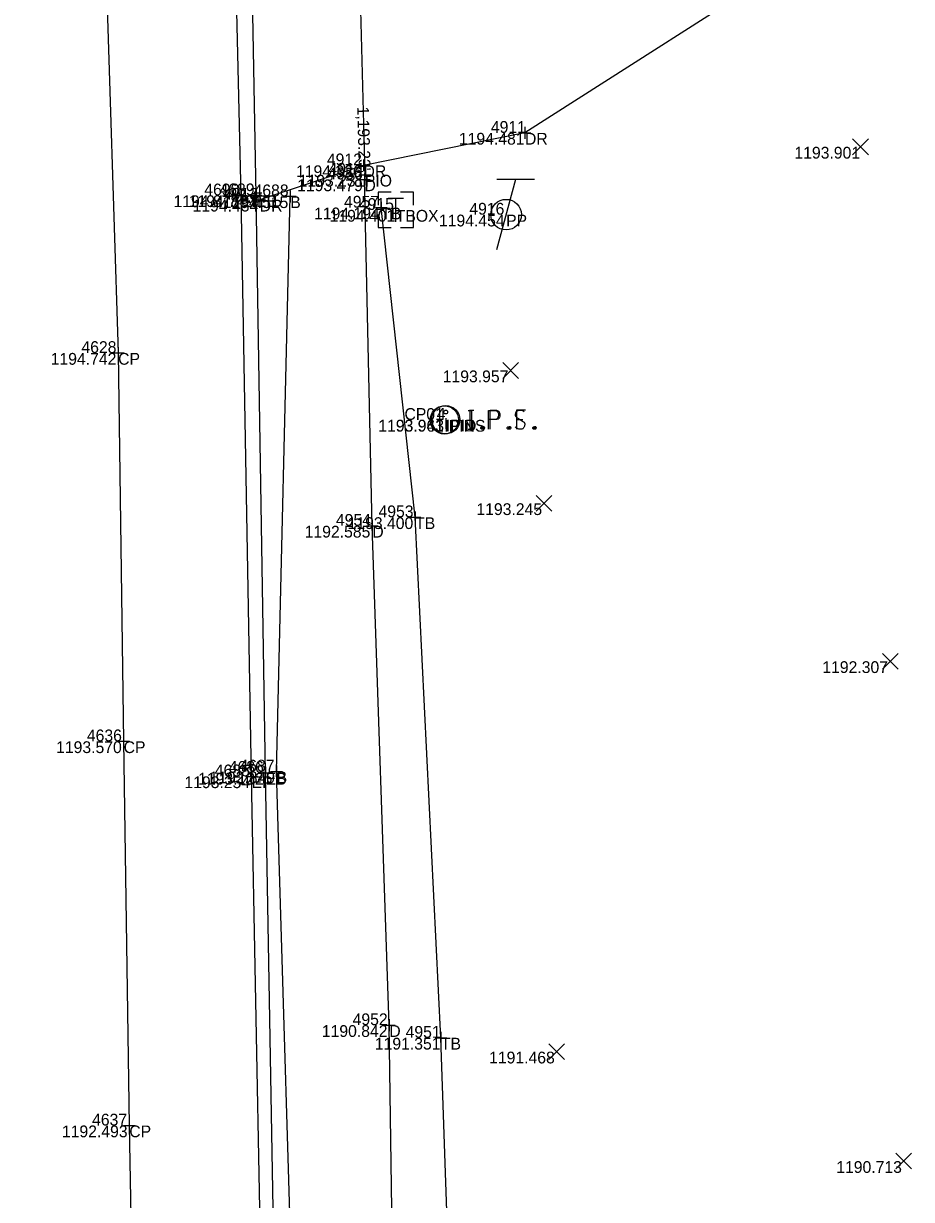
# Model space of a CAD drawing. Extents: x 2044996 to 2050343, y 455232 to 458054.
# Drawn here: x 2047638.7 to 2047714.1, y 456240.2 to 456340.1 of the extents above; entities that cross this region are included whole.
import ezdxf

# ---------------------------------------------------------------- set-up
doc = ezdxf.new("R2010")
doc.units = 0
for name, color, linetype in [('DR_X_Ditch', 7, 'Continuous'), ('DR_X_Elev_Flow', 7, 'Continuous'), ('DR_X_Storm_Sewer', 7, 'Continuous'), ('DT_X_Contour_Minor', 7, 'Continuous'), ('DT_X_Contour_Text', 7, 'Continuous'), ('DT_X_Spot_Elev', 7, 'Continuous'), ('DT_X_TIN_Hull', 7, 'Continuous'), ('DT_X_Triangles', 7, 'Continuous'), ('DT_X_Void', 7, 'Continuous'), ('PV_X_COP', 7, 'Continuous'), ('PV_X_Driveway', 7, 'Continuous'), ('PV_X_EOP', 7, 'Continuous'), ('PV_X_Shoulder_Aggregate', 7, 'Continuous'), ('SC_Scratch1', 7, 'Continuous'), ('SV_P_Mon_Cells_Set', 7, 'Continuous'), ('SV_X_Break_Lines', 7, 'Continuous'), ('SV_X_Top_of_Bank', 7, 'Continuous'), ('UT_X_Electric_Cells', 7, 'Continuous'), ('XS_X_Ground_Line', 7, 'Continuous')]:
    doc.layers.add(name, color=color, linetype=linetype)

msp = doc.modelspace()

# ---------------------------------------------------------------- linework, layer by layer
at = {"layer": 'DR_X_Ditch'}
msp.add_lwpolyline([(2047671.117, 455981.962), (2047672.134, 456029.553), (2047671.987, 456077.978), (2047672.773, 456128.444), (2047671.222, 456171.914), (2047670.3, 456214.023), (2047669.722, 456255.021), (2047668.278, 456297.447), (2047667.609, 456326.875)], dxfattribs=at)
at = {"layer": 'DR_X_Elev_Flow'}
for p, q in [((2047667.145, 456327.273), (2047668.145, 456327.273)), ((2047667.645, 456327.773), (2047667.645, 456326.773)), ((2047667.645, 456327.273), (2047667.645, 456327.273))]:
    msp.add_line(p, q, dxfattribs=at)
at = {"layer": 'DR_X_Storm_Sewer'}
msp.add_line((2047665.559, 456406.889), (2047667.645, 456327.273), dxfattribs=at)
at = {"layer": 'DT_X_Spot_Elev'}
for p, q in [((2047709.079, 456328.976), (2047710.413, 456330.311)), ((2047709.079, 456330.311), (2047710.413, 456328.976)), ((2047679.369, 456309.975), (2047680.703, 456311.31)), ((2047679.369, 456311.31), (2047680.703, 456309.975)), ((2047682.199, 456298.694), (2047683.533, 456300.029)), ((2047682.199, 456300.029), (2047683.533, 456298.694)), ((2047711.612, 456285.272), (2047712.945, 456286.607)), ((2047711.612, 456286.607), (2047712.945, 456285.272)), ((2047683.267, 456252.103), (2047684.6, 456253.438)), ((2047683.267, 456253.438), (2047684.6, 456252.103)), ((2047712.742, 456242.801), (2047714.075, 456244.136)), ((2047712.742, 456244.136), (2047714.075, 456242.801))]:
    msp.add_line(p, q, dxfattribs=at)
at = {"layer": 'DT_X_TIN_Hull'}
for p, q in [((2047669.617, 456325.283), (2047670.917, 456325.283)), ((2047670.267, 456323.283), (2047670.267, 456325.283)), ((2047670.267, 456324.283), (2047670.267, 456324.283))]:
    msp.add_line(p, q, dxfattribs=at)
for points in [[(2047669.867, 456325.783), (2047668.767, 456325.783), (2047668.767, 456324.683)], [(2047671.767, 456324.683), (2047671.767, 456325.783), (2047670.667, 456325.783)], [(2047668.767, 456323.883), (2047668.767, 456322.783), (2047669.867, 456322.783)], [(2047670.667, 456322.783), (2047671.767, 456322.783), (2047671.767, 456323.883)]]:
    msp.add_lwpolyline(points, dxfattribs=at)
at = {"layer": 'DT_X_Void'}
for p, q in [((2047681.246, 456331.331), (2047681.246, 456330.331)), ((2047680.746, 456330.831), (2047681.746, 456330.831)), ((2047681.246, 456330.831), (2047681.246, 456330.831)), ((2047667.534, 456328.571), (2047667.534, 456327.571)), ((2047667.034, 456328.071), (2047668.034, 456328.071)), ((2047667.534, 456328.071), (2047667.534, 456328.071)), ((2047667.609, 456327.375), (2047667.609, 456326.375)), ((2047667.109, 456326.875), (2047668.109, 456326.875)), ((2047667.609, 456326.875), (2047667.609, 456326.875)), ((2047656.627, 456325.518), (2047657.627, 456325.518)), ((2047657.127, 456326.018), (2047657.127, 456325.018)), ((2047657.127, 456325.518), (2047657.127, 456325.518)), ((2047657.9, 456325.527), (2047658.9, 456325.527)), ((2047658.4, 456326.027), (2047658.4, 456325.027)), ((2047658.4, 456325.527), (2047658.4, 456325.527)), ((2047658.717, 456325.649), (2047658.717, 456324.649)), ((2047660.811, 456325.444), (2047661.811, 456325.444)), ((2047661.311, 456325.944), (2047661.311, 456324.944)), ((2047661.311, 456325.444), (2047661.311, 456325.444)), ((2047658.217, 456325.149), (2047659.217, 456325.149)), ((2047658.717, 456325.149), (2047658.717, 456325.149)), ((2047668.537, 456324.48), (2047669.537, 456324.48)), ((2047669.037, 456324.98), (2047669.037, 456323.98)), ((2047669.037, 456324.48), (2047669.037, 456324.48)), ((2047646.69, 456312.631), (2047646.69, 456311.631)), ((2047646.19, 456312.131), (2047647.19, 456312.131)), ((2047646.69, 456312.131), (2047646.69, 456312.131)), ((2047671.914, 456298.673), (2047671.914, 456297.673)), ((2047667.778, 456297.447), (2047668.778, 456297.447)), ((2047668.278, 456297.947), (2047668.278, 456296.947)), ((2047668.278, 456297.447), (2047668.278, 456297.447)), ((2047671.414, 456298.173), (2047672.414, 456298.173)), ((2047671.914, 456298.173), (2047671.914, 456298.173)), ((2047647.156, 456279.638), (2047647.156, 456278.638)), ((2047646.656, 456279.138), (2047647.656, 456279.138)), ((2047647.156, 456279.138), (2047647.156, 456279.138)), ((2047658.025, 456276.66), (2047658.025, 456275.66)), ((2047658.711, 456276.462), (2047659.711, 456276.462)), ((2047659.211, 456276.962), (2047659.211, 456275.962)), ((2047659.211, 456276.462), (2047659.211, 456276.462)), ((2047659.655, 456276.569), (2047660.655, 456276.569)), ((2047660.155, 456277.069), (2047660.155, 456276.069)), ((2047660.155, 456276.569), (2047660.155, 456276.569)), ((2047657.525, 456276.16), (2047658.525, 456276.16)), ((2047658.025, 456276.16), (2047658.025, 456276.16)), ((2047669.722, 456255.521), (2047669.722, 456254.521)), ((2047669.222, 456255.021), (2047670.222, 456255.021)), ((2047669.722, 456255.021), (2047669.722, 456255.021)), ((2047674.107, 456254.449), (2047674.107, 456253.449)), ((2047673.607, 456253.949), (2047674.607, 456253.949)), ((2047674.107, 456253.949), (2047674.107, 456253.949)), ((2047647.137, 456246.496), (2047648.137, 456246.496)), ((2047647.637, 456246.996), (2047647.637, 456245.996)), ((2047647.637, 456246.496), (2047647.637, 456246.496))]:
    msp.add_line(p, q, dxfattribs=at)
at = {"layer": 'PV_X_COP'}
msp.add_lwpolyline([(2047638.653, 456684.973), (2047639.719, 456638.627), (2047640.673, 456589.237), (2047641.66, 456540.181), (2047642.518, 456493.325), (2047643.706, 456444.37), (2047644.365, 456399.724), (2047645.213, 456358.38), (2047646.69, 456312.131), (2047647.156, 456279.138), (2047647.637, 456246.496), (2047648.014, 456224.803), (2047648.981, 456176.778), (2047649.645, 456128.981), (2047650.619, 456077.985), (2047651.479, 456030.793), (2047652.412, 455980.916), (2047652.554, 455976.287)], dxfattribs=at)
at = {"layer": 'PV_X_Driveway'}
msp.add_lwpolyline([(2047705.842, 456346.56), (2047681.246, 456330.831), (2047667.534, 456328.071), (2047658.717, 456325.149)], dxfattribs=at)
at = {"layer": 'PV_X_EOP'}
for p, q in [((2047657.127, 456325.518), (2047656.157, 456369.535)), ((2047658.025, 456276.16), (2047657.127, 456325.518)), ((2047659.025, 456223.208), (2047658.025, 456276.16))]:
    msp.add_line(p, q, dxfattribs=at)
at = {"layer": 'PV_X_Shoulder_Aggregate'}
msp.add_lwpolyline([(2047664.762, 455980.108), (2047663.648, 456028.131), (2047662.657, 456078.835), (2047661.937, 456126.71), (2047661.179, 456172.398), (2047660.152, 456223.294), (2047659.211, 456276.462), (2047658.4, 456325.527), (2047657.583, 456370.169), (2047657.311, 456406.35), (2047656.24, 456454.322), (2047655.337, 456499.11), (2047654.467, 456545.858), (2047653.303, 456590.715), (2047651.942, 456638.925), (2047650.861, 456688.179)], dxfattribs=at)
at = {"layer": 'SV_P_Mon_Cells_Set'}
for points in [[(2047676.417, 456307.245), (2047676.77, 456307.245)], [(2047676.594, 456305.645), (2047676.594, 456307.245)], [(2047678.159, 456305.645), (2047678.159, 456307.245), (2047678.688, 456307.245), (2047678.743, 456307.233), (2047678.82, 456307.208), (2047678.853, 456307.182), (2047678.886, 456307.157), (2047678.93, 456307.094), (2047678.964, 456307.031), (2047678.986, 456306.93), (2047678.986, 456306.779), (2047678.975, 456306.729), (2047678.952, 456306.653), (2047678.908, 456306.565), (2047678.864, 456306.527), (2047678.831, 456306.502), (2047678.776, 456306.477), (2047678.688, 456306.464), (2047678.159, 456306.464)], [(2047681.168, 456307.132), (2047681.146, 456307.157), (2047681.113, 456307.182), (2047681.014, 456307.22), (2047680.893, 456307.245), (2047680.804, 456307.245), (2047680.771, 456307.245), (2047680.628, 456307.208), (2047680.507, 456307.132), (2047680.43, 456307.031), (2047680.408, 456306.93), (2047680.408, 456306.855), (2047680.43, 456306.754), (2047680.518, 456306.666), (2047681.124, 456306.288), (2047681.179, 456306.238), (2047681.201, 456306.187), (2047681.223, 456306.112), (2047681.223, 456306.036), (2047681.212, 456305.961), (2047681.201, 456305.91), (2047681.179, 456305.847), (2047681.157, 456305.797), (2047681.135, 456305.759), (2047681.102, 456305.721), (2047681.069, 456305.696), (2047681.025, 456305.671), (2047680.992, 456305.658), (2047680.893, 456305.645), (2047680.738, 456305.645), (2047680.639, 456305.671), (2047680.496, 456305.759), (2047680.408, 456305.835)], [(2047676.417, 456305.645), (2047676.77, 456305.645)], [(2047677.553, 456305.86), (2047677.608, 456305.86), (2047677.641, 456305.835), (2047677.674, 456305.784), (2047677.674, 456305.721), (2047677.641, 456305.671), (2047677.608, 456305.645), (2047677.553, 456305.645), (2047677.52, 456305.671), (2047677.487, 456305.721), (2047677.487, 456305.784), (2047677.52, 456305.835), (2047677.553, 456305.86)], [(2047679.801, 456305.86), (2047679.856, 456305.86), (2047679.89, 456305.835), (2047679.923, 456305.784), (2047679.923, 456305.721), (2047679.89, 456305.671), (2047679.856, 456305.645), (2047679.801, 456305.645), (2047679.768, 456305.671), (2047679.735, 456305.721), (2047679.735, 456305.784), (2047679.768, 456305.835), (2047679.801, 456305.86)], [(2047681.984, 456305.86), (2047682.039, 456305.86), (2047682.072, 456305.835), (2047682.105, 456305.784), (2047682.105, 456305.721), (2047682.072, 456305.671), (2047682.039, 456305.645), (2047681.984, 456305.645), (2047681.951, 456305.671), (2047681.918, 456305.721), (2047681.918, 456305.784), (2047681.951, 456305.835), (2047681.984, 456305.86)]]:
    msp.add_lwpolyline(points, dxfattribs=at)
msp.add_circle((2047674.398, 456306.444), 1.2, dxfattribs=at)
at = {"layer": 'SV_X_Break_Lines'}
msp.add_lwpolyline([(2047666.11, 455980.305), (2047665.473, 456028.089), (2047664.308, 456079.327), (2047663.538, 456127.154), (2047662.435, 456172.396), (2047661.761, 456223.096), (2047660.155, 456276.569), (2047661.311, 456325.444)], dxfattribs=at)
at = {"layer": 'SV_X_Top_of_Bank'}
msp.add_lwpolyline([(2047680.581, 455981.434), (2047678.203, 456027.621), (2047677.779, 456077.869), (2047678.046, 456126.417), (2047677.443, 456172.34), (2047675.483, 456213.851), (2047674.107, 456253.949), (2047671.914, 456298.173), (2047669.037, 456324.48)], dxfattribs=at)
at = {"layer": 'UT_X_Electric_Cells'}
for p, q in [((2047680.446, 456326.882), (2047678.839, 456320.882)), ((2047682.046, 456326.882), (2047678.846, 456326.882))]:
    msp.add_line(p, q, dxfattribs=at)
msp.add_circle((2047679.643, 456323.882), 1.3, dxfattribs=at)
at = {"layer": 'XS_X_Ground_Line'}
msp.add_line((2047674.515, 456306.579), (2047674.515, 456305.695), dxfattribs=at)
for points in [[(2047676.546, 456307.262), (2047676.898, 456307.262)], [(2047676.722, 456305.662), (2047676.722, 456307.262)], [(2047678.287, 456305.662), (2047678.287, 456307.262), (2047678.816, 456307.262), (2047678.872, 456307.249), (2047678.949, 456307.224), (2047678.982, 456307.199), (2047679.015, 456307.174), (2047679.059, 456307.111), (2047679.092, 456307.048), (2047679.114, 456306.947), (2047679.114, 456306.796), (2047679.103, 456306.746), (2047679.081, 456306.67), (2047679.037, 456306.582), (2047678.993, 456306.544), (2047678.96, 456306.519), (2047678.905, 456306.494), (2047678.816, 456306.481), (2047678.287, 456306.481)], [(2047681.297, 456307.262), (2047680.536, 456307.262), (2047680.536, 456305.662)], [(2047680.536, 456306.481), (2047681.076, 456306.481)], [(2047676.546, 456305.662), (2047676.898, 456305.662)], [(2047677.681, 456305.876), (2047677.736, 456305.876), (2047677.769, 456305.851), (2047677.802, 456305.801), (2047677.802, 456305.738), (2047677.769, 456305.687), (2047677.736, 456305.662), (2047677.681, 456305.662), (2047677.648, 456305.687), (2047677.615, 456305.738), (2047677.615, 456305.801), (2047677.648, 456305.851), (2047677.681, 456305.876)], [(2047679.93, 456305.876), (2047679.985, 456305.876), (2047680.018, 456305.851), (2047680.051, 456305.801), (2047680.051, 456305.738), (2047680.018, 456305.687), (2047679.985, 456305.662), (2047679.93, 456305.662), (2047679.897, 456305.687), (2047679.864, 456305.738), (2047679.864, 456305.801), (2047679.897, 456305.851), (2047679.93, 456305.876)], [(2047682.079, 456305.876), (2047682.134, 456305.876), (2047682.167, 456305.851), (2047682.2, 456305.801), (2047682.2, 456305.738), (2047682.167, 456305.687), (2047682.134, 456305.662), (2047682.079, 456305.662), (2047682.046, 456305.687), (2047682.013, 456305.738), (2047682.013, 456305.801), (2047682.046, 456305.851), (2047682.079, 456305.876)]]:
    msp.add_lwpolyline(points, dxfattribs=at)
for centre, radius in [((2047674.515, 456306.462), 1.2), ((2047674.515, 456307.114), 0.16)]:
    msp.add_circle(centre, radius, dxfattribs=at)

# ---------------------------------------------------------------- texts
at = {"layer": 'DT_X_Contour_Minor'}
for s, p in [('1194.481', (2047675.632, 456329.831)), ('1193.901', (2047704.133, 456328.644)), ('1194.326', (2047661.797, 456327.071)), ('1193.231', (2047662.031, 456326.273)), ('1193.479', (2047661.895, 456325.875)), ('1194.878', (2047651.395, 456324.518)), ('1194.749', (2047652.686, 456324.527)), ('1194.515', (2047655.567, 456324.444)), ('1194.434', (2047653.012, 456324.149)), ('1194.194', (2047663.332, 456323.48)), ('1194.401', (2047664.653, 456323.283)), ('1194.454', (2047673.939, 456322.882)), ('1194.742', (2047640.961, 456311.131)), ('1193.957', (2047674.26, 456309.643)), ('1193.961', (2047668.785, 456305.444)), ('1193.943', (2047668.793, 456305.462)), ('1193.245', (2047677.122, 456298.361)), ('1192.585', (2047662.534, 456296.447)), ('1193.400', (2047666.18, 456297.173)), ('1192.307', (2047706.502, 456284.94)), ('1193.570', (2047641.422, 456278.138)), ('1193.122', (2047653.481, 456275.462)), ('1192.849', (2047654.441, 456275.569)), ('1193.254', (2047652.321, 456275.16)), ('1190.842', (2047663.992, 456254.021)), ('1191.351', (2047668.494, 456252.949)), ('1191.468', (2047678.201, 456251.77)), ('1192.493', (2047641.915, 456245.496)), ('1190.713', (2047707.686, 456242.468))]:
    msp.add_text(s, height=1, dxfattribs=at).set_placement(p)
at = {"layer": 'DT_X_Contour_Text'}
for s, p in [('DR', (2047681.246, 456329.831)), ('DR', (2047667.534, 456327.071)), ('PIO', (2047667.645, 456326.273)), ('D', (2047667.609, 456325.875)), ('EP', (2047657.127, 456324.518)), ('EB', (2047658.4, 456324.527)), ('B', (2047661.311, 456324.444)), ('DR', (2047658.717, 456324.149)), ('TB', (2047669.037, 456323.48)), ('TBOX', (2047670.267, 456323.283)), ('PP', (2047679.643, 456322.882)), ('CP', (2047646.69, 456311.131)), ('IPINS', (2047674.398, 456305.444)), ('IPID', (2047674.515, 456305.462)), ('D', (2047668.278, 456296.447)), ('TB', (2047671.914, 456297.173)), ('CP', (2047647.156, 456278.138)), ('EB', (2047659.211, 456275.462)), ('B', (2047660.155, 456275.569)), ('EP', (2047658.025, 456275.16)), ('D', (2047669.722, 456254.021)), ('TB', (2047674.107, 456252.949)), ('CP', (2047647.637, 456245.496))]:
    msp.add_text(s, height=1, dxfattribs=at).set_placement(p)
at = {"layer": 'DT_X_Triangles'}
for s, p in [('4911', (2047678.35, 456330.831)), ('4912', (2047664.419, 456328.071)), ('4914', (2047664.555, 456327.273)), ('4956', (2047664.487, 456326.875)), ('4690', (2047654.008, 456325.518)), ('4689', (2047655.301, 456325.527)), ('4688', (2047658.193, 456325.444)), ('4913', (2047655.608, 456325.149)), ('4957', (2047665.875, 456324.48)), ('4915', (2047667.137, 456324.283)), ('4916', (2047676.52, 456323.882)), ('4628', (2047643.572, 456312.131)), ('CP01', (2047671.011, 456306.444)), ('4', (2047673.755, 456306.462)), ('4954', (2047665.188, 456297.447)), ('4953', (2047668.806, 456298.173)), ('4636', (2047644.034, 456279.138)), ('4686', (2047656.088, 456276.462)), ('4687', (2047656.993, 456276.569)), ('4685', (2047654.896, 456276.16)), ('4952', (2047666.607, 456255.021)), ('4951', (2047671.108, 456253.949)), ('4637', (2047644.476, 456246.496))]:
    msp.add_text(s, height=1, dxfattribs=at).set_placement(p)
at = {"layer": 'SC_Scratch1'}
msp.add_text("1,193.23'", height=1, rotation=271.5003, dxfattribs=at).set_placement((2047666.993, 456333.056))

doc.saveas('drawing.dxf')
